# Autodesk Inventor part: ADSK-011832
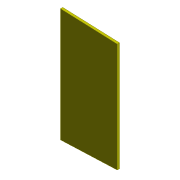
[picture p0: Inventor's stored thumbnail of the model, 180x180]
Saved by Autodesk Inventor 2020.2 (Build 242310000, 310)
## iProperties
Created: 1999-11
Part Number: ADSK-011832
Document SubType Name: Modeling
Designer: sspink
Material: Générique
Density: 1 g/cm^3
Appearance: Gelb
Mass: 32.631 g
Surface Area: 230.774 cm^2
Volume: 32.631 cm^3
Control State: 0
Checked Out: False
Last Check In By: sspink
Last Check In Date: 1999-12-22
Master: False
Shininess: 0.0
Length Units: 11269
Angle Units: 11279
Time Units: 11290
Mass Units: 11283
Length Display Precision: 3
Angle Display Precision: 2
Compacted: True
Dimensions: 149x3x74,5 mm
Mass: 0,033 kg
VLT_Material: Generisch
Density: 0.0
Volumn: 0.0
Area: 0.0
PropertySet Name: Model Information
Author: sspink
Revision Number: -
Title: ADSK-011832
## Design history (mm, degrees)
node "Solide1"
  node "Extrusion1" dims "d1" = 3, "d2" = 0
sketch "Sketch1"
  geometry: L1 (175.617, 55.898)-(175.617, -87.102); L2 (175.617, 55.898)-(101.117, 58.898); L3 (101.117, 58.898)-(101.117, -90.102); L4 (101.117, -90.102)-(175.617, -87.102); L5 (101.117, -15.602)-(175.617, -15.602)
  constraints: 10 end point, 2 midpoint, 1 parallel, 1 perpendicular
  dimensions: "d3" = 143 distance of L1.start L1.end; "d4" = 149 distance of L2.end L3.end; "d5" = 74.5 distance between parallel lines of L1 L3
workplane "Work Plane1"
workplane "Work Plane2"
workplane "Work Plane3"
workaxis "Work Axis1"
node "Corps solides"
node "Corps surfaciques"
other parameters: "d7" = 90 deg, "d8" = 76.2, "d9" = 182.40375
